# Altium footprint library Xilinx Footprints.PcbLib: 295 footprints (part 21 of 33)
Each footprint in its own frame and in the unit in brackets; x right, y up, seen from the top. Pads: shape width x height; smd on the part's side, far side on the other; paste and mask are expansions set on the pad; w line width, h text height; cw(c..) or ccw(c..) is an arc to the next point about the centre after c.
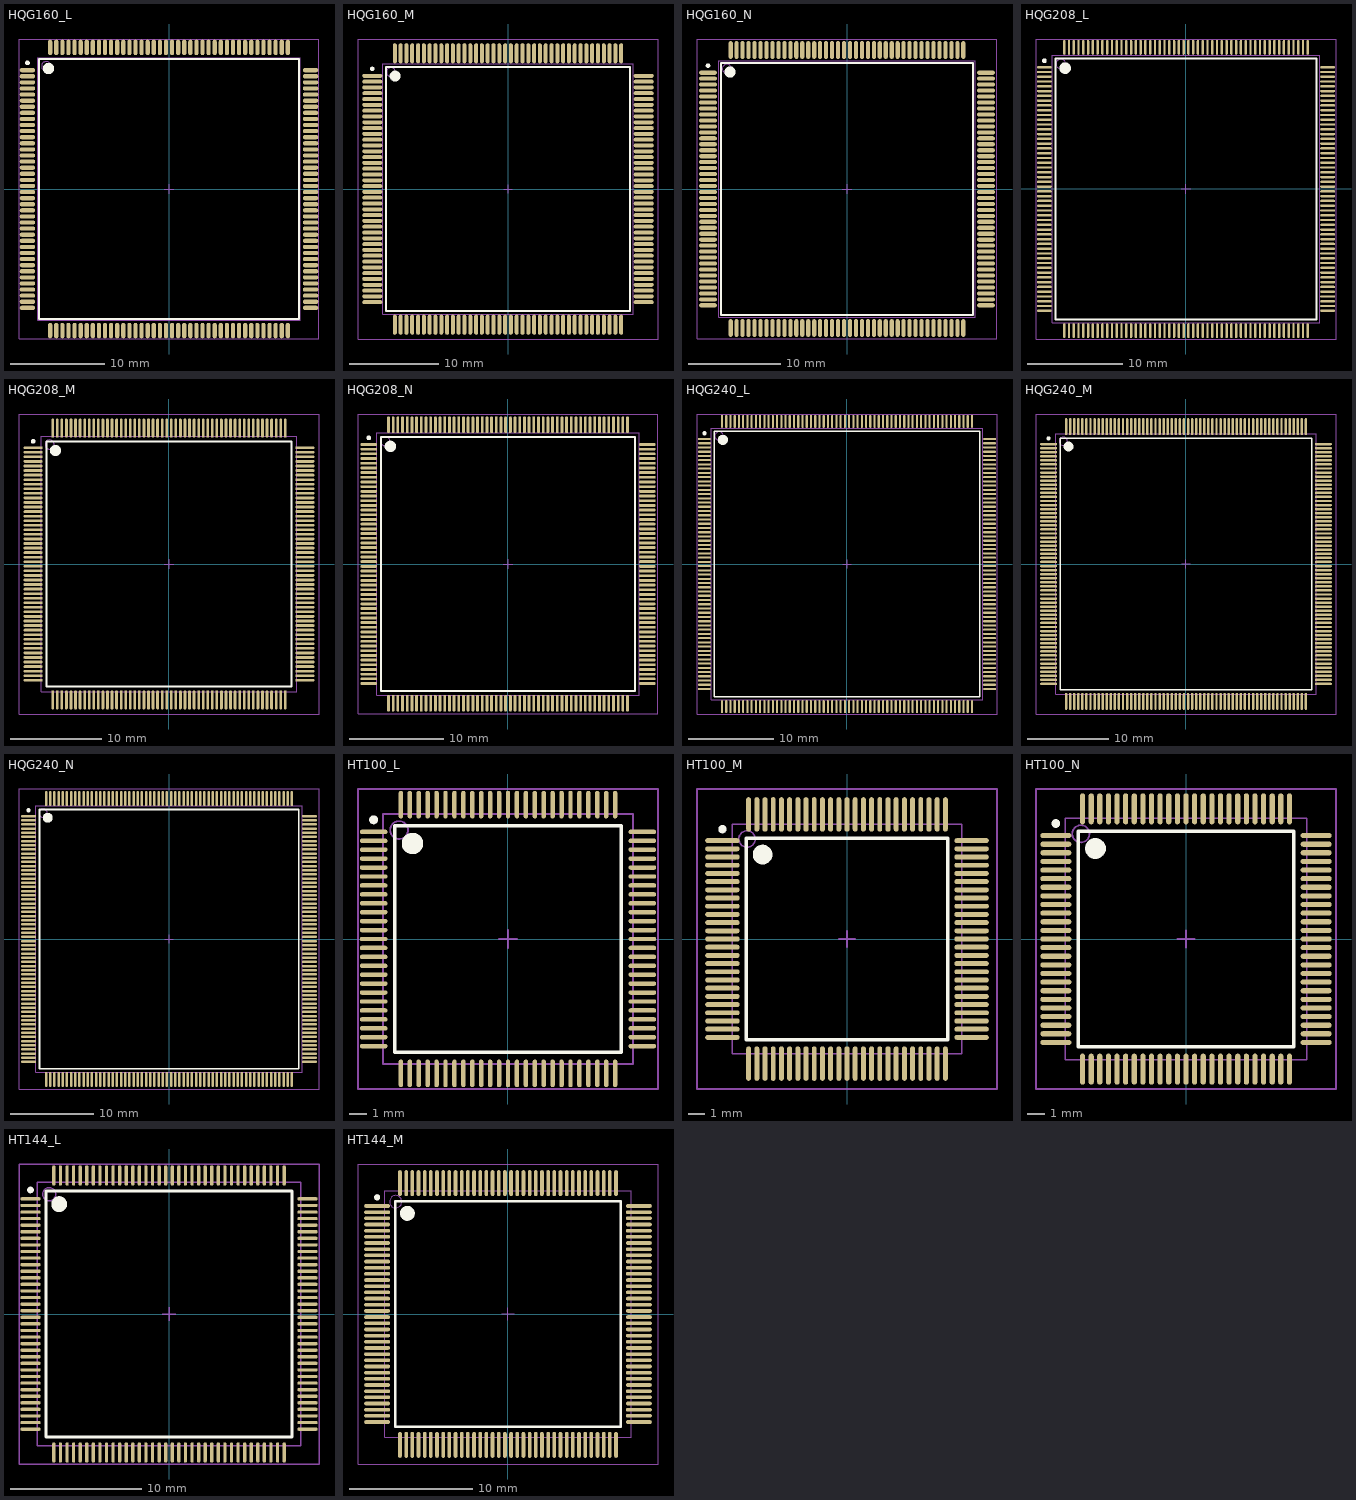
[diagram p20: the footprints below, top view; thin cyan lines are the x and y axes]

## HQG160_L [mm] "160-Pin Heat Sink Quad Flat Pack (HQG160) - Pb-Free, IPC High Density"
height 4.1
pads (160):
  oval 1.65x0.45 smd: 1(-15.1,12.675) 2(-15.1,12.025) 3(-15.1,11.375) 4(-15.1,10.725) 5(-15.1,10.075) 6(-15.1,9.425) 7(-15.1,8.775) 8(-15.1,8.125) 9(-15.1,7.475) 10(-15.1,6.825) 11(-15.1,6.175) 12(-15.1,5.525) 13(-15.1,4.875) 14(-15.1,4.225) 15(-15.1,3.575) 16(-15.1,2.925) 17(-15.1,2.275) 18(-15.1,1.625) 19(-15.1,0.975) 20(-15.1,0.325) 21(-15.1,-0.325) 22(-15.1,-0.975) 23(-15.1,-1.625) 24(-15.1,-2.275) 25(-15.1,-2.925) 26(-15.1,-3.575) 27(-15.1,-4.225) 28(-15.1,-4.875) 29(-15.1,-5.525) 30(-15.1,-6.175) 31(-15.1,-6.825) 32(-15.1,-7.475) 33(-15.1,-8.125) 34(-15.1,-8.775) 35(-15.1,-9.425) 36(-15.1,-10.075) 37(-15.1,-10.725) 38(-15.1,-11.375) 39(-15.1,-12.025) 40(-15.1,-12.675) 81(15.1,-12.675) 82(15.1,-12.025) 83(15.1,-11.375) 84(15.1,-10.725) 85(15.1,-10.075) 86(15.1,-9.425) 87(15.1,-8.775) 88(15.1,-8.125) 89(15.1,-7.475) 90(15.1,-6.825) 91(15.1,-6.175) 92(15.1,-5.525) 93(15.1,-4.875) 94(15.1,-4.225) 95(15.1,-3.575) 96(15.1,-2.925) 97(15.1,-2.275) 98(15.1,-1.625) 99(15.1,-0.975) 100(15.1,-0.325) 101(15.1,0.325) 102(15.1,0.975) 103(15.1,1.625) 104(15.1,2.275) 105(15.1,2.925) 106(15.1,3.575) 107(15.1,4.225) 108(15.1,4.875) 109(15.1,5.525) 110(15.1,6.175) 111(15.1,6.825) 112(15.1,7.475) 113(15.1,8.125) 114(15.1,8.775) 115(15.1,9.425) 116(15.1,10.075) 117(15.1,10.725) 118(15.1,11.375) 119(15.1,12.025) 120(15.1,12.675)
  oval 0.45x1.65 smd: 41(-12.675,-15.1) 42(-12.025,-15.1) 43(-11.375,-15.1) 44(-10.725,-15.1) 45(-10.075,-15.1) 46(-9.425,-15.1) 47(-8.775,-15.1) 48(-8.125,-15.1) 49(-7.475,-15.1) 50(-6.825,-15.1) 51(-6.175,-15.1) 52(-5.525,-15.1) 53(-4.875,-15.1) 54(-4.225,-15.1) 55(-3.575,-15.1) 56(-2.925,-15.1) 57(-2.275,-15.1) 58(-1.625,-15.1) 59(-0.975,-15.1) 60(-0.325,-15.1) 61(0.325,-15.1) 62(0.975,-15.1) 63(1.625,-15.1) 64(2.275,-15.1) 65(2.925,-15.1) 66(3.575,-15.1) 67(4.225,-15.1) 68(4.875,-15.1) 69(5.525,-15.1) 70(6.175,-15.1) 71(6.825,-15.1) 72(7.475,-15.1) 73(8.125,-15.1) 74(8.775,-15.1) 75(9.425,-15.1) 76(10.075,-15.1) 77(10.725,-15.1) 78(11.375,-15.1) 79(12.025,-15.1) 80(12.675,-15.1) 121(12.675,15.1) 122(12.025,15.1) 123(11.375,15.1) 124(10.725,15.1) 125(10.075,15.1) 126(9.425,15.1) 127(8.775,15.1) 128(8.125,15.1) 129(7.475,15.1) 130(6.825,15.1) 131(6.175,15.1) 132(5.525,15.1) 133(4.875,15.1) 134(4.225,15.1) 135(3.575,15.1) 136(2.925,15.1) 137(2.275,15.1) 138(1.625,15.1) 139(0.975,15.1) 140(0.325,15.1) 141(-0.325,15.1) 142(-0.975,15.1) 143(-1.625,15.1) 144(-2.275,15.1) 145(-2.925,15.1) 146(-3.575,15.1) 147(-4.225,15.1) 148(-4.875,15.1) 149(-5.525,15.1) 150(-6.175,15.1) 151(-6.825,15.1) 152(-7.475,15.1) 153(-8.125,15.1) 154(-8.775,15.1) 155(-9.425,15.1) 156(-10.075,15.1) 157(-10.725,15.1) 158(-11.375,15.1) 159(-12.025,15.1) 160(-12.675,15.1)
Top Overlay:
  circle w0.6: c-12.85,12.85 r0.3
  circle w0.25: c-15.1,13.45 r0.125
  lines w0.2: -13.85,-13.85 13.85,-13.85 13.85,13.85 -13.85,13.85 -13.85,-13.85
Mechanical 13:
  circle w0.1: c-13.1,13.1 r0.5
  lines w0.1: -14,-14 14,-14 14,14 -14,14 -14,-14
Mechanical 15:
  lines w0.1: -0.5,0 0.5,0 ; 0,-0.5 0,0.5 ; -16,-16 16,-16 16,16 -16,16 -16,-16
3D body: height 4.1, standoff 0, extent -14,-14 14,14

## HQG160_M [mm] "160-Pin Heat Sink Quad Flat Pack (HQG160) - Pb-Free, IPC Low Density"
height 4.1
pads (160):
  oval 2.25x0.45 smd: 1(-15.2,12.675) 2(-15.2,12.025) 3(-15.2,11.375) 4(-15.2,10.725) 5(-15.2,10.075) 6(-15.2,9.425) 7(-15.2,8.775) 8(-15.2,8.125) 9(-15.2,7.475) 10(-15.2,6.825) 11(-15.2,6.175) 12(-15.2,5.525) 13(-15.2,4.875) 14(-15.2,4.225) 15(-15.2,3.575) 16(-15.2,2.925) 17(-15.2,2.275) 18(-15.2,1.625) 19(-15.2,0.975) 20(-15.2,0.325) 21(-15.2,-0.325) 22(-15.2,-0.975) 23(-15.2,-1.625) 24(-15.2,-2.275) 25(-15.2,-2.925) 26(-15.2,-3.575) 27(-15.2,-4.225) 28(-15.2,-4.875) 29(-15.2,-5.525) 30(-15.2,-6.175) 31(-15.2,-6.825) 32(-15.2,-7.475) 33(-15.2,-8.125) 34(-15.2,-8.775) 35(-15.2,-9.425) 36(-15.2,-10.075) 37(-15.2,-10.725) 38(-15.2,-11.375) 39(-15.2,-12.025) 40(-15.2,-12.675) 81(15.2,-12.675) 82(15.2,-12.025) 83(15.2,-11.375) 84(15.2,-10.725) 85(15.2,-10.075) 86(15.2,-9.425) 87(15.2,-8.775) 88(15.2,-8.125) 89(15.2,-7.475) 90(15.2,-6.825) 91(15.2,-6.175) 92(15.2,-5.525) 93(15.2,-4.875) 94(15.2,-4.225) 95(15.2,-3.575) 96(15.2,-2.925) 97(15.2,-2.275) 98(15.2,-1.625) 99(15.2,-0.975) 100(15.2,-0.325) 101(15.2,0.325) 102(15.2,0.975) 103(15.2,1.625) 104(15.2,2.275) 105(15.2,2.925) 106(15.2,3.575) 107(15.2,4.225) 108(15.2,4.875) 109(15.2,5.525) 110(15.2,6.175) 111(15.2,6.825) 112(15.2,7.475) 113(15.2,8.125) 114(15.2,8.775) 115(15.2,9.425) 116(15.2,10.075) 117(15.2,10.725) 118(15.2,11.375) 119(15.2,12.025) 120(15.2,12.675)
  oval 0.45x2.25 smd: 41(-12.675,-15.2) 42(-12.025,-15.2) 43(-11.375,-15.2) 44(-10.725,-15.2) 45(-10.075,-15.2) 46(-9.425,-15.2) 47(-8.775,-15.2) 48(-8.125,-15.2) 49(-7.475,-15.2) 50(-6.825,-15.2) 51(-6.175,-15.2) 52(-5.525,-15.2) 53(-4.875,-15.2) 54(-4.225,-15.2) 55(-3.575,-15.2) 56(-2.925,-15.2) 57(-2.275,-15.2) 58(-1.625,-15.2) 59(-0.975,-15.2) 60(-0.325,-15.2) 61(0.325,-15.2) 62(0.975,-15.2) 63(1.625,-15.2) 64(2.275,-15.2) 65(2.925,-15.2) 66(3.575,-15.2) 67(4.225,-15.2) 68(4.875,-15.2) 69(5.525,-15.2) 70(6.175,-15.2) 71(6.825,-15.2) 72(7.475,-15.2) 73(8.125,-15.2) 74(8.775,-15.2) 75(9.425,-15.2) 76(10.075,-15.2) 77(10.725,-15.2) 78(11.375,-15.2) 79(12.025,-15.2) 80(12.675,-15.2) 121(12.675,15.2) 122(12.025,15.2) 123(11.375,15.2) 124(10.725,15.2) 125(10.075,15.2) 126(9.425,15.2) 127(8.775,15.2) 128(8.125,15.2) 129(7.475,15.2) 130(6.825,15.2) 131(6.175,15.2) 132(5.525,15.2) 133(4.875,15.2) 134(4.225,15.2) 135(3.575,15.2) 136(2.925,15.2) 137(2.275,15.2) 138(1.625,15.2) 139(0.975,15.2) 140(0.325,15.2) 141(-0.325,15.2) 142(-0.975,15.2) 143(-1.625,15.2) 144(-2.275,15.2) 145(-2.925,15.2) 146(-3.575,15.2) 147(-4.225,15.2) 148(-4.875,15.2) 149(-5.525,15.2) 150(-6.175,15.2) 151(-6.825,15.2) 152(-7.475,15.2) 153(-8.125,15.2) 154(-8.775,15.2) 155(-9.425,15.2) 156(-10.075,15.2) 157(-10.725,15.2) 158(-11.375,15.2) 159(-12.025,15.2) 160(-12.675,15.2)
Top Overlay:
  circle w0.6: c-12.65,12.65 r0.3
  circle w0.25: c-15.2,13.45 r0.125
  lines w0.2: -13.65,-13.65 13.65,-13.65 13.65,13.65 -13.65,13.65 -13.65,-13.65
Mechanical 13:
  circle w0.1: c-13.1,13.1 r0.5
  lines w0.1: -14,-14 14,-14 14,14 -14,14 -14,-14
Mechanical 15:
  lines w0.1: -0.5,0 0.5,0 ; 0,-0.5 0,0.5 ; -16.8,-16.8 16.8,-16.8 16.8,16.8 -16.8,16.8 -16.8,-16.8
3D body: height 4.1, standoff 0, extent -14,-14 14,14

## HQG160_N [mm] "160-Pin Heat Sink Quad Flat Pack (HQG160) - Pb-Free, IPC Medium Density"
height 4.1
pads (160):
  oval 1.95x0.45 smd: 1(-15.15,12.675) 2(-15.15,12.025) 3(-15.15,11.375) 4(-15.15,10.725) 5(-15.15,10.075) 6(-15.15,9.425) 7(-15.15,8.775) 8(-15.15,8.125) 9(-15.15,7.475) 10(-15.15,6.825) 11(-15.15,6.175) 12(-15.15,5.525) 13(-15.15,4.875) 14(-15.15,4.225) 15(-15.15,3.575) 16(-15.15,2.925) 17(-15.15,2.275) 18(-15.15,1.625) 19(-15.15,0.975) 20(-15.15,0.325) 21(-15.15,-0.325) 22(-15.15,-0.975) 23(-15.15,-1.625) 24(-15.15,-2.275) 25(-15.15,-2.925) 26(-15.15,-3.575) 27(-15.15,-4.225) 28(-15.15,-4.875) 29(-15.15,-5.525) 30(-15.15,-6.175) 31(-15.15,-6.825) 32(-15.15,-7.475) 33(-15.15,-8.125) 34(-15.15,-8.775) 35(-15.15,-9.425) 36(-15.15,-10.075) 37(-15.15,-10.725) 38(-15.15,-11.375) 39(-15.15,-12.025) 40(-15.15,-12.675) 81(15.15,-12.675) 82(15.15,-12.025) 83(15.15,-11.375) 84(15.15,-10.725) 85(15.15,-10.075) 86(15.15,-9.425) 87(15.15,-8.775) 88(15.15,-8.125) 89(15.15,-7.475) 90(15.15,-6.825) 91(15.15,-6.175) 92(15.15,-5.525) 93(15.15,-4.875) 94(15.15,-4.225) 95(15.15,-3.575) 96(15.15,-2.925) 97(15.15,-2.275) 98(15.15,-1.625) 99(15.15,-0.975) 100(15.15,-0.325) 101(15.15,0.325) 102(15.15,0.975) 103(15.15,1.625) 104(15.15,2.275) 105(15.15,2.925) 106(15.15,3.575) 107(15.15,4.225) 108(15.15,4.875) 109(15.15,5.525) 110(15.15,6.175) 111(15.15,6.825) 112(15.15,7.475) 113(15.15,8.125) 114(15.15,8.775) 115(15.15,9.425) 116(15.15,10.075) 117(15.15,10.725) 118(15.15,11.375) 119(15.15,12.025) 120(15.15,12.675)
  oval 0.45x1.95 smd: 41(-12.675,-15.15) 42(-12.025,-15.15) 43(-11.375,-15.15) 44(-10.725,-15.15) 45(-10.075,-15.15) 46(-9.425,-15.15) 47(-8.775,-15.15) 48(-8.125,-15.15) 49(-7.475,-15.15) 50(-6.825,-15.15) 51(-6.175,-15.15) 52(-5.525,-15.15) 53(-4.875,-15.15) 54(-4.225,-15.15) 55(-3.575,-15.15) 56(-2.925,-15.15) 57(-2.275,-15.15) 58(-1.625,-15.15) 59(-0.975,-15.15) 60(-0.325,-15.15) 61(0.325,-15.15) 62(0.975,-15.15) 63(1.625,-15.15) 64(2.275,-15.15) 65(2.925,-15.15) 66(3.575,-15.15) 67(4.225,-15.15) 68(4.875,-15.15) 69(5.525,-15.15) 70(6.175,-15.15) 71(6.825,-15.15) 72(7.475,-15.15) 73(8.125,-15.15) 74(8.775,-15.15) 75(9.425,-15.15) 76(10.075,-15.15) 77(10.725,-15.15) 78(11.375,-15.15) 79(12.025,-15.15) 80(12.675,-15.15) 121(12.675,15.15) 122(12.025,15.15) 123(11.375,15.15) 124(10.725,15.15) 125(10.075,15.15) 126(9.425,15.15) 127(8.775,15.15) 128(8.125,15.15) 129(7.475,15.15) 130(6.825,15.15) 131(6.175,15.15) 132(5.525,15.15) 133(4.875,15.15) 134(4.225,15.15) 135(3.575,15.15) 136(2.925,15.15) 137(2.275,15.15) 138(1.625,15.15) 139(0.975,15.15) 140(0.325,15.15) 141(-0.325,15.15) 142(-0.975,15.15) 143(-1.625,15.15) 144(-2.275,15.15) 145(-2.925,15.15) 146(-3.575,15.15) 147(-4.225,15.15) 148(-4.875,15.15) 149(-5.525,15.15) 150(-6.175,15.15) 151(-6.825,15.15) 152(-7.475,15.15) 153(-8.125,15.15) 154(-8.775,15.15) 155(-9.425,15.15) 156(-10.075,15.15) 157(-10.725,15.15) 158(-11.375,15.15) 159(-12.025,15.15) 160(-12.675,15.15)
Top Overlay:
  circle w0.6: c-12.75,12.75 r0.3
  circle w0.25: c-15.15,13.45 r0.125
  lines w0.2: -13.75,-13.75 13.75,-13.75 13.75,13.75 -13.75,13.75 -13.75,-13.75
Mechanical 13:
  circle w0.1: c-13.1,13.1 r0.5
  lines w0.1: -14,-14 14,-14 14,14 -14,14 -14,-14
Mechanical 15:
  lines w0.1: -0.5,0 0.5,0 ; 0,-0.5 0,0.5 ; -16.35,-16.35 16.35,-16.35 16.35,16.35 -16.35,16.35 -16.35,-16.35
3D body: height 4.1, standoff 0, extent -14,-14 14,14

## HQG208_L [mm] "208-Pin Heat Sink Quad Flat Pack (HQG208) - Pb-Free, IPC High Density"
height 4.1
pads (208):
  oval 1.55x0.25 smd: 1(-14.825,12.75) 2(-14.825,12.25) 3(-14.825,11.75) 4(-14.825,11.25) 5(-14.825,10.75) 6(-14.825,10.25) 7(-14.825,9.75) 8(-14.825,9.25) 9(-14.825,8.75) 10(-14.825,8.25) 11(-14.825,7.75) 12(-14.825,7.25) 13(-14.825,6.75) 14(-14.825,6.25) 15(-14.825,5.75) 16(-14.825,5.25) 17(-14.825,4.75) 18(-14.825,4.25) 19(-14.825,3.75) 20(-14.825,3.25) 21(-14.825,2.75) 22(-14.825,2.25) 23(-14.825,1.75) 24(-14.825,1.25) 25(-14.825,0.75) 26(-14.825,0.25) 27(-14.825,-0.25) 28(-14.825,-0.75) 29(-14.825,-1.25) 30(-14.825,-1.75) 31(-14.825,-2.25) 32(-14.825,-2.75) 33(-14.825,-3.25) 34(-14.825,-3.75) 35(-14.825,-4.25) 36(-14.825,-4.75) 37(-14.825,-5.25) 38(-14.825,-5.75) 39(-14.825,-6.25) 40(-14.825,-6.75) 41(-14.825,-7.25) 42(-14.825,-7.75) 43(-14.825,-8.25) 44(-14.825,-8.75) 45(-14.825,-9.25) 46(-14.825,-9.75) 47(-14.825,-10.25) 48(-14.825,-10.75) 49(-14.825,-11.25) 50(-14.825,-11.75) 51(-14.825,-12.25) 52(-14.825,-12.75) 105(14.825,-12.75) 106(14.825,-12.25) 107(14.825,-11.75) 108(14.825,-11.25) 109(14.825,-10.75) 110(14.825,-10.25) 111(14.825,-9.75) 112(14.825,-9.25) 113(14.825,-8.75) 114(14.825,-8.25) 115(14.825,-7.75) 116(14.825,-7.25) 117(14.825,-6.75) 118(14.825,-6.25) 119(14.825,-5.75) 120(14.825,-5.25) 121(14.825,-4.75) 122(14.825,-4.25) 123(14.825,-3.75) 124(14.825,-3.25) 125(14.825,-2.75) 126(14.825,-2.25) 127(14.825,-1.75) 128(14.825,-1.25) 129(14.825,-0.75) 130(14.825,-0.25) 131(14.825,0.25) 132(14.825,0.75) 133(14.825,1.25) 134(14.825,1.75) 135(14.825,2.25) 136(14.825,2.75) 137(14.825,3.25) 138(14.825,3.75) 139(14.825,4.25) 140(14.825,4.75) 141(14.825,5.25) 142(14.825,5.75) 143(14.825,6.25) 144(14.825,6.75) 145(14.825,7.25) 146(14.825,7.75) 147(14.825,8.25) 148(14.825,8.75) 149(14.825,9.25) 150(14.825,9.75) 151(14.825,10.25) 152(14.825,10.75) 153(14.825,11.25) 154(14.825,11.75) 155(14.825,12.25) 156(14.825,12.75)
  oval 0.25x1.55 smd: 53(-12.75,-14.825) 54(-12.25,-14.825) 55(-11.75,-14.825) 56(-11.25,-14.825) 57(-10.75,-14.825) 58(-10.25,-14.825) 59(-9.75,-14.825) 60(-9.25,-14.825) 61(-8.75,-14.825) 62(-8.25,-14.825) 63(-7.75,-14.825) 64(-7.25,-14.825) 65(-6.75,-14.825) 66(-6.25,-14.825) 67(-5.75,-14.825) 68(-5.25,-14.825) 69(-4.75,-14.825) 70(-4.25,-14.825) 71(-3.75,-14.825) 72(-3.25,-14.825) 73(-2.75,-14.825) 74(-2.25,-14.825) 75(-1.75,-14.825) 76(-1.25,-14.825) 77(-0.75,-14.825) 78(-0.25,-14.825) 79(0.25,-14.825) 80(0.75,-14.825) 81(1.25,-14.825) 82(1.75,-14.825) 83(2.25,-14.825) 84(2.75,-14.825) 85(3.25,-14.825) 86(3.75,-14.825) 87(4.25,-14.825) 88(4.75,-14.825) 89(5.25,-14.825) 90(5.75,-14.825) 91(6.25,-14.825) 92(6.75,-14.825) 93(7.25,-14.825) 94(7.75,-14.825) 95(8.25,-14.825) 96(8.75,-14.825) 97(9.25,-14.825) 98(9.75,-14.825) 99(10.25,-14.825) 100(10.75,-14.825) 101(11.25,-14.825) 102(11.75,-14.825) 103(12.25,-14.825) 104(12.75,-14.825) 157(12.75,14.825) 158(12.25,14.825) 159(11.75,14.825) 160(11.25,14.825) 161(10.75,14.825) 162(10.25,14.825) 163(9.75,14.825) 164(9.25,14.825) 165(8.75,14.825) 166(8.25,14.825) 167(7.75,14.825) 168(7.25,14.825) 169(6.75,14.825) 170(6.25,14.825) 171(5.75,14.825) 172(5.25,14.825) 173(4.75,14.825) 174(4.25,14.825) 175(3.75,14.825) 176(3.25,14.825) 177(2.75,14.825) 178(2.25,14.825) 179(1.75,14.825) 180(1.25,14.825) 181(0.75,14.825) 182(0.25,14.825) 183(-0.25,14.825) 184(-0.75,14.825) 185(-1.25,14.825) 186(-1.75,14.825) 187(-2.25,14.825) 188(-2.75,14.825) 189(-3.25,14.825) 190(-3.75,14.825) 191(-4.25,14.825) 192(-4.75,14.825) 193(-5.25,14.825) 194(-5.75,14.825) 195(-6.25,14.825) 196(-6.75,14.825) 197(-7.25,14.825) 198(-7.75,14.825) 199(-8.25,14.825) 200(-8.75,14.825) 201(-9.25,14.825) 202(-9.75,14.825) 203(-10.25,14.825) 204(-10.75,14.825) 205(-11.25,14.825) 206(-11.75,14.825) 207(-12.25,14.825) 208(-12.75,14.825)
Top Overlay:
  circle w0.6: c-12.65,12.65 r0.3
  circle w0.25: c-14.825,13.425 r0.125
  lines w0.2: -13.65,-13.65 13.65,-13.65 13.65,13.65 -13.65,13.65 -13.65,-13.65
Mechanical 13:
  circle w0.1: c-13.1,13.1 r0.5
  lines w0.1: -14,-14 14,-14 14,14 -14,14 -14,-14
Mechanical 15:
  lines w0.1: -0.5,0 0.5,0 ; 0,-0.5 0,0.5 ; -15.7,-15.7 15.7,-15.7 15.7,15.7 -15.7,15.7 -15.7,-15.7
3D body: height 4.1, standoff 0, extent -14,-14 14,14

## HQG208_M [mm] "208-Pin Heat Sink Quad Flat Pack (HQG208) - Pb-Free, IPC Low Density"
height 4.1
pads (208):
  oval 2.1x0.3 smd: 1(-14.9,12.75) 2(-14.9,12.25) 3(-14.9,11.75) 4(-14.9,11.25) 5(-14.9,10.75) 6(-14.9,10.25) 7(-14.9,9.75) 8(-14.9,9.25) 9(-14.9,8.75) 10(-14.9,8.25) 11(-14.9,7.75) 12(-14.9,7.25) 13(-14.9,6.75) 14(-14.9,6.25) 15(-14.9,5.75) 16(-14.9,5.25) 17(-14.9,4.75) 18(-14.9,4.25) 19(-14.9,3.75) 20(-14.9,3.25) 21(-14.9,2.75) 22(-14.9,2.25) 23(-14.9,1.75) 24(-14.9,1.25) 25(-14.9,0.75) 26(-14.9,0.25) 27(-14.9,-0.25) 28(-14.9,-0.75) 29(-14.9,-1.25) 30(-14.9,-1.75) 31(-14.9,-2.25) 32(-14.9,-2.75) 33(-14.9,-3.25) 34(-14.9,-3.75) 35(-14.9,-4.25) 36(-14.9,-4.75) 37(-14.9,-5.25) 38(-14.9,-5.75) 39(-14.9,-6.25) 40(-14.9,-6.75) 41(-14.9,-7.25) 42(-14.9,-7.75) 43(-14.9,-8.25) 44(-14.9,-8.75) 45(-14.9,-9.25) 46(-14.9,-9.75) 47(-14.9,-10.25) 48(-14.9,-10.75) 49(-14.9,-11.25) 50(-14.9,-11.75) 51(-14.9,-12.25) 52(-14.9,-12.75) 105(14.9,-12.75) 106(14.9,-12.25) 107(14.9,-11.75) 108(14.9,-11.25) 109(14.9,-10.75) 110(14.9,-10.25) 111(14.9,-9.75) 112(14.9,-9.25) 113(14.9,-8.75) 114(14.9,-8.25) 115(14.9,-7.75) 116(14.9,-7.25) 117(14.9,-6.75) 118(14.9,-6.25) 119(14.9,-5.75) 120(14.9,-5.25) 121(14.9,-4.75) 122(14.9,-4.25) 123(14.9,-3.75) 124(14.9,-3.25) 125(14.9,-2.75) 126(14.9,-2.25) 127(14.9,-1.75) 128(14.9,-1.25) 129(14.9,-0.75) 130(14.9,-0.25) 131(14.9,0.25) 132(14.9,0.75) 133(14.9,1.25) 134(14.9,1.75) 135(14.9,2.25) 136(14.9,2.75) 137(14.9,3.25) 138(14.9,3.75) 139(14.9,4.25) 140(14.9,4.75) 141(14.9,5.25) 142(14.9,5.75) 143(14.9,6.25) 144(14.9,6.75) 145(14.9,7.25) 146(14.9,7.75) 147(14.9,8.25) 148(14.9,8.75) 149(14.9,9.25) 150(14.9,9.75) 151(14.9,10.25) 152(14.9,10.75) 153(14.9,11.25) 154(14.9,11.75) 155(14.9,12.25) 156(14.9,12.75)
  oval 0.3x2.1 smd: 53(-12.75,-14.9) 54(-12.25,-14.9) 55(-11.75,-14.9) 56(-11.25,-14.9) 57(-10.75,-14.9) 58(-10.25,-14.9) 59(-9.75,-14.9) 60(-9.25,-14.9) 61(-8.75,-14.9) 62(-8.25,-14.9) 63(-7.75,-14.9) 64(-7.25,-14.9) 65(-6.75,-14.9) 66(-6.25,-14.9) 67(-5.75,-14.9) 68(-5.25,-14.9) 69(-4.75,-14.9) 70(-4.25,-14.9) 71(-3.75,-14.9) 72(-3.25,-14.9) 73(-2.75,-14.9) 74(-2.25,-14.9) 75(-1.75,-14.9) 76(-1.25,-14.9) 77(-0.75,-14.9) 78(-0.25,-14.9) 79(0.25,-14.9) 80(0.75,-14.9) 81(1.25,-14.9) 82(1.75,-14.9) 83(2.25,-14.9) 84(2.75,-14.9) 85(3.25,-14.9) 86(3.75,-14.9) 87(4.25,-14.9) 88(4.75,-14.9) 89(5.25,-14.9) 90(5.75,-14.9) 91(6.25,-14.9) 92(6.75,-14.9) 93(7.25,-14.9) 94(7.75,-14.9) 95(8.25,-14.9) 96(8.75,-14.9) 97(9.25,-14.9) 98(9.75,-14.9) 99(10.25,-14.9) 100(10.75,-14.9) 101(11.25,-14.9) 102(11.75,-14.9) 103(12.25,-14.9) 104(12.75,-14.9) 157(12.75,14.9) 158(12.25,14.9) 159(11.75,14.9) 160(11.25,14.9) 161(10.75,14.9) 162(10.25,14.9) 163(9.75,14.9) 164(9.25,14.9) 165(8.75,14.9) 166(8.25,14.9) 167(7.75,14.9) 168(7.25,14.9) 169(6.75,14.9) 170(6.25,14.9) 171(5.75,14.9) 172(5.25,14.9) 173(4.75,14.9) 174(4.25,14.9) 175(3.75,14.9) 176(3.25,14.9) 177(2.75,14.9) 178(2.25,14.9) 179(1.75,14.9) 180(1.25,14.9) 181(0.75,14.9) 182(0.25,14.9) 183(-0.25,14.9) 184(-0.75,14.9) 185(-1.25,14.9) 186(-1.75,14.9) 187(-2.25,14.9) 188(-2.75,14.9) 189(-3.25,14.9) 190(-3.75,14.9) 191(-4.25,14.9) 192(-4.75,14.9) 193(-5.25,14.9) 194(-5.75,14.9) 195(-6.25,14.9) 196(-6.75,14.9) 197(-7.25,14.9) 198(-7.75,14.9) 199(-8.25,14.9) 200(-8.75,14.9) 201(-9.25,14.9) 202(-9.75,14.9) 203(-10.25,14.9) 204(-10.75,14.9) 205(-11.25,14.9) 206(-11.75,14.9) 207(-12.25,14.9) 208(-12.75,14.9)
Top Overlay:
  circle w0.6: c-12.45,12.45 r0.3
  circle w0.25: c-14.9,13.45 r0.125
  lines w0.2: -13.45,-13.45 13.45,-13.45 13.45,13.45 -13.45,13.45 -13.45,-13.45
Mechanical 13:
  circle w0.1: c-13.1,13.1 r0.5
  lines w0.1: -14,-14 14,-14 14,14 -14,14 -14,-14
Mechanical 15:
  lines w0.1: -0.5,0 0.5,0 ; 0,-0.5 0,0.5 ; -16.45,-16.45 16.45,-16.45 16.45,16.45 -16.45,16.45 -16.45,-16.45
3D body: height 4.1, standoff 0, extent -14,-14 14,14

## HQG208_N [mm] "208-Pin Heat Sink Quad Flat Pack (HQG208) - Pb-Free, IPC Medium Density"
height 4.1
pads (208):
  oval 1.8x0.3 smd: 1(-14.85,12.75) 2(-14.85,12.25) 3(-14.85,11.75) 4(-14.85,11.25) 5(-14.85,10.75) 6(-14.85,10.25) 7(-14.85,9.75) 8(-14.85,9.25) 9(-14.85,8.75) 10(-14.85,8.25) 11(-14.85,7.75) 12(-14.85,7.25) 13(-14.85,6.75) 14(-14.85,6.25) 15(-14.85,5.75) 16(-14.85,5.25) 17(-14.85,4.75) 18(-14.85,4.25) 19(-14.85,3.75) 20(-14.85,3.25) 21(-14.85,2.75) 22(-14.85,2.25) 23(-14.85,1.75) 24(-14.85,1.25) 25(-14.85,0.75) 26(-14.85,0.25) 27(-14.85,-0.25) 28(-14.85,-0.75) 29(-14.85,-1.25) 30(-14.85,-1.75) 31(-14.85,-2.25) 32(-14.85,-2.75) 33(-14.85,-3.25) 34(-14.85,-3.75) 35(-14.85,-4.25) 36(-14.85,-4.75) 37(-14.85,-5.25) 38(-14.85,-5.75) 39(-14.85,-6.25) 40(-14.85,-6.75) 41(-14.85,-7.25) 42(-14.85,-7.75) 43(-14.85,-8.25) 44(-14.85,-8.75) 45(-14.85,-9.25) 46(-14.85,-9.75) 47(-14.85,-10.25) 48(-14.85,-10.75) 49(-14.85,-11.25) 50(-14.85,-11.75) 51(-14.85,-12.25) 52(-14.85,-12.75) 105(14.85,-12.75) 106(14.85,-12.25) 107(14.85,-11.75) 108(14.85,-11.25) 109(14.85,-10.75) 110(14.85,-10.25) 111(14.85,-9.75) 112(14.85,-9.25) 113(14.85,-8.75) 114(14.85,-8.25) 115(14.85,-7.75) 116(14.85,-7.25) 117(14.85,-6.75) 118(14.85,-6.25) 119(14.85,-5.75) 120(14.85,-5.25) 121(14.85,-4.75) 122(14.85,-4.25) 123(14.85,-3.75) 124(14.85,-3.25) 125(14.85,-2.75) 126(14.85,-2.25) 127(14.85,-1.75) 128(14.85,-1.25) 129(14.85,-0.75) 130(14.85,-0.25) 131(14.85,0.25) 132(14.85,0.75) 133(14.85,1.25) 134(14.85,1.75) 135(14.85,2.25) 136(14.85,2.75) 137(14.85,3.25) 138(14.85,3.75) 139(14.85,4.25) 140(14.85,4.75) 141(14.85,5.25) 142(14.85,5.75) 143(14.85,6.25) 144(14.85,6.75) 145(14.85,7.25) 146(14.85,7.75) 147(14.85,8.25) 148(14.85,8.75) 149(14.85,9.25) 150(14.85,9.75) 151(14.85,10.25) 152(14.85,10.75) 153(14.85,11.25) 154(14.85,11.75) 155(14.85,12.25) 156(14.85,12.75)
  oval 0.3x1.8 smd: 53(-12.75,-14.85) 54(-12.25,-14.85) 55(-11.75,-14.85) 56(-11.25,-14.85) 57(-10.75,-14.85) 58(-10.25,-14.85) 59(-9.75,-14.85) 60(-9.25,-14.85) 61(-8.75,-14.85) 62(-8.25,-14.85) 63(-7.75,-14.85) 64(-7.25,-14.85) 65(-6.75,-14.85) 66(-6.25,-14.85) 67(-5.75,-14.85) 68(-5.25,-14.85) 69(-4.75,-14.85) 70(-4.25,-14.85) 71(-3.75,-14.85) 72(-3.25,-14.85) 73(-2.75,-14.85) 74(-2.25,-14.85) 75(-1.75,-14.85) 76(-1.25,-14.85) 77(-0.75,-14.85) 78(-0.25,-14.85) 79(0.25,-14.85) 80(0.75,-14.85) 81(1.25,-14.85) 82(1.75,-14.85) 83(2.25,-14.85) 84(2.75,-14.85) 85(3.25,-14.85) 86(3.75,-14.85) 87(4.25,-14.85) 88(4.75,-14.85) 89(5.25,-14.85) 90(5.75,-14.85) 91(6.25,-14.85) 92(6.75,-14.85) 93(7.25,-14.85) 94(7.75,-14.85) 95(8.25,-14.85) 96(8.75,-14.85) 97(9.25,-14.85) 98(9.75,-14.85) 99(10.25,-14.85) 100(10.75,-14.85) 101(11.25,-14.85) 102(11.75,-14.85) 103(12.25,-14.85) 104(12.75,-14.85) 157(12.75,14.85) 158(12.25,14.85) 159(11.75,14.85) 160(11.25,14.85) 161(10.75,14.85) 162(10.25,14.85) 163(9.75,14.85) 164(9.25,14.85) 165(8.75,14.85) 166(8.25,14.85) 167(7.75,14.85) 168(7.25,14.85) 169(6.75,14.85) 170(6.25,14.85) 171(5.75,14.85) 172(5.25,14.85) 173(4.75,14.85) 174(4.25,14.85) 175(3.75,14.85) 176(3.25,14.85) 177(2.75,14.85) 178(2.25,14.85) 179(1.75,14.85) 180(1.25,14.85) 181(0.75,14.85) 182(0.25,14.85) 183(-0.25,14.85) 184(-0.75,14.85) 185(-1.25,14.85) 186(-1.75,14.85) 187(-2.25,14.85) 188(-2.75,14.85) 189(-3.25,14.85) 190(-3.75,14.85) 191(-4.25,14.85) 192(-4.75,14.85) 193(-5.25,14.85) 194(-5.75,14.85) 195(-6.25,14.85) 196(-6.75,14.85) 197(-7.25,14.85) 198(-7.75,14.85) 199(-8.25,14.85) 200(-8.75,14.85) 201(-9.25,14.85) 202(-9.75,14.85) 203(-10.25,14.85) 204(-10.75,14.85) 205(-11.25,14.85) 206(-11.75,14.85) 207(-12.25,14.85) 208(-12.75,14.85)
Top Overlay:
  circle w0.6: c-12.55,12.55 r0.3
  circle w0.25: c-14.85,13.45 r0.125
  lines w0.2: -13.55,-13.55 13.55,-13.55 13.55,13.55 -13.55,13.55 -13.55,-13.55
Mechanical 13:
  circle w0.1: c-13.1,13.1 r0.5
  lines w0.1: -14,-14 14,-14 14,14 -14,14 -14,-14
Mechanical 15:
  lines w0.1: -0.5,0 0.5,0 ; 0,-0.5 0,0.5 ; -16,-16 16,-16 16,16 -16,16 -16,-16
3D body: height 4.1, standoff 0, extent -14,-14 14,14

## HQG240_L [mm] "240-Pin Heat Sink Quad Flat Pack (HQG240) - Pb-Free, IPC High Density"
height 4.1
pads (240):
  oval 1.55x0.25 smd: 1(-16.825,14.75) 2(-16.825,14.25) 3(-16.825,13.75) 4(-16.825,13.25) 5(-16.825,12.75) 6(-16.825,12.25) 7(-16.825,11.75) 8(-16.825,11.25) 9(-16.825,10.75) 10(-16.825,10.25) 11(-16.825,9.75) 12(-16.825,9.25) 13(-16.825,8.75) 14(-16.825,8.25) 15(-16.825,7.75) 16(-16.825,7.25) 17(-16.825,6.75) 18(-16.825,6.25) 19(-16.825,5.75) 20(-16.825,5.25) 21(-16.825,4.75) 22(-16.825,4.25) 23(-16.825,3.75) 24(-16.825,3.25) 25(-16.825,2.75) 26(-16.825,2.25) 27(-16.825,1.75) 28(-16.825,1.25) 29(-16.825,0.75) 30(-16.825,0.25) 31(-16.825,-0.25) 32(-16.825,-0.75) 33(-16.825,-1.25) 34(-16.825,-1.75) 35(-16.825,-2.25) 36(-16.825,-2.75) 37(-16.825,-3.25) 38(-16.825,-3.75) 39(-16.825,-4.25) 40(-16.825,-4.75) 41(-16.825,-5.25) 42(-16.825,-5.75) 43(-16.825,-6.25) 44(-16.825,-6.75) 45(-16.825,-7.25) 46(-16.825,-7.75) 47(-16.825,-8.25) 48(-16.825,-8.75) 49(-16.825,-9.25) 50(-16.825,-9.75) 51(-16.825,-10.25) 52(-16.825,-10.75) 53(-16.825,-11.25) 54(-16.825,-11.75) 55(-16.825,-12.25) 56(-16.825,-12.75) 57(-16.825,-13.25) 58(-16.825,-13.75) 59(-16.825,-14.25) 60(-16.825,-14.75) 121(16.825,-14.75) 122(16.825,-14.25) 123(16.825,-13.75) 124(16.825,-13.25) 125(16.825,-12.75) 126(16.825,-12.25) 127(16.825,-11.75) 128(16.825,-11.25) 129(16.825,-10.75) 130(16.825,-10.25) 131(16.825,-9.75) 132(16.825,-9.25) 133(16.825,-8.75) 134(16.825,-8.25) 135(16.825,-7.75) 136(16.825,-7.25) 137(16.825,-6.75) 138(16.825,-6.25) 139(16.825,-5.75) 140(16.825,-5.25) 141(16.825,-4.75) 142(16.825,-4.25) 143(16.825,-3.75) 144(16.825,-3.25) 145(16.825,-2.75) 146(16.825,-2.25) 147(16.825,-1.75) 148(16.825,-1.25) 149(16.825,-0.75) 150(16.825,-0.25) 151(16.825,0.25) 152(16.825,0.75) 153(16.825,1.25) 154(16.825,1.75) 155(16.825,2.25) 156(16.825,2.75) 157(16.825,3.25) 158(16.825,3.75) 159(16.825,4.25) 160(16.825,4.75) 161(16.825,5.25) 162(16.825,5.75) 163(16.825,6.25) 164(16.825,6.75) 165(16.825,7.25) 166(16.825,7.75) 167(16.825,8.25) 168(16.825,8.75) 169(16.825,9.25) 170(16.825,9.75) 171(16.825,10.25) 172(16.825,10.75) 173(16.825,11.25) 174(16.825,11.75) 175(16.825,12.25) 176(16.825,12.75) 177(16.825,13.25) 178(16.825,13.75) 179(16.825,14.25) 180(16.825,14.75)
  oval 0.25x1.55 smd: 61(-14.75,-16.825) 62(-14.25,-16.825) 63(-13.75,-16.825) 64(-13.25,-16.825) 65(-12.75,-16.825) 66(-12.25,-16.825) 67(-11.75,-16.825) 68(-11.25,-16.825) 69(-10.75,-16.825) 70(-10.25,-16.825) 71(-9.75,-16.825) 72(-9.25,-16.825) 73(-8.75,-16.825) 74(-8.25,-16.825) 75(-7.75,-16.825) 76(-7.25,-16.825) 77(-6.75,-16.825) 78(-6.25,-16.825) 79(-5.75,-16.825) 80(-5.25,-16.825) 81(-4.75,-16.825) 82(-4.25,-16.825) 83(-3.75,-16.825) 84(-3.25,-16.825) 85(-2.75,-16.825) 86(-2.25,-16.825) 87(-1.75,-16.825) 88(-1.25,-16.825) 89(-0.75,-16.825) 90(-0.25,-16.825) 91(0.25,-16.825) 92(0.75,-16.825) 93(1.25,-16.825) 94(1.75,-16.825) 95(2.25,-16.825) 96(2.75,-16.825) 97(3.25,-16.825) 98(3.75,-16.825) 99(4.25,-16.825) 100(4.75,-16.825) 101(5.25,-16.825) 102(5.75,-16.825) 103(6.25,-16.825) 104(6.75,-16.825) 105(7.25,-16.825) 106(7.75,-16.825) 107(8.25,-16.825) 108(8.75,-16.825) 109(9.25,-16.825) 110(9.75,-16.825) 111(10.25,-16.825) 112(10.75,-16.825) 113(11.25,-16.825) 114(11.75,-16.825) 115(12.25,-16.825) 116(12.75,-16.825) 117(13.25,-16.825) 118(13.75,-16.825) 119(14.25,-16.825) 120(14.75,-16.825) 181(14.75,16.825) 182(14.25,16.825) 183(13.75,16.825) 184(13.25,16.825) 185(12.75,16.825) 186(12.25,16.825) 187(11.75,16.825) 188(11.25,16.825) 189(10.75,16.825) 190(10.25,16.825) 191(9.75,16.825) 192(9.25,16.825) 193(8.75,16.825) 194(8.25,16.825) 195(7.75,16.825) 196(7.25,16.825) 197(6.75,16.825) 198(6.25,16.825) 199(5.75,16.825) 200(5.25,16.825) 201(4.75,16.825) 202(4.25,16.825) 203(3.75,16.825) 204(3.25,16.825) 205(2.75,16.825) 206(2.25,16.825) 207(1.75,16.825) 208(1.25,16.825) 209(0.75,16.825) 210(0.25,16.825) 211(-0.25,16.825) 212(-0.75,16.825) 213(-1.25,16.825) 214(-1.75,16.825) 215(-2.25,16.825) 216(-2.75,16.825) 217(-3.25,16.825) 218(-3.75,16.825) 219(-4.25,16.825) 220(-4.75,16.825) 221(-5.25,16.825) 222(-5.75,16.825) 223(-6.25,16.825) 224(-6.75,16.825) 225(-7.25,16.825) 226(-7.75,16.825) 227(-8.25,16.825) 228(-8.75,16.825) 229(-9.25,16.825) 230(-9.75,16.825) 231(-10.25,16.825) 232(-10.75,16.825) 233(-11.25,16.825) 234(-11.75,16.825) 235(-12.25,16.825) 236(-12.75,16.825) 237(-13.25,16.825) 238(-13.75,16.825) 239(-14.25,16.825) 240(-14.75,16.825)
Top Overlay:
  circle w0.6: c-14.65,14.65 r0.3
  circle w0.25: c-16.825,15.425 r0.125
  lines w0.2: -15.65,-15.65 15.65,-15.65 15.65,15.65 -15.65,15.65 -15.65,-15.65
Mechanical 13:
  circle w0.1: c-15.1,15.1 r0.5
  lines w0.1: -16,-16 16,-16 16,16 -16,16 -16,-16
Mechanical 15:
  lines w0.1: -0.5,0 0.5,0 ; 0,-0.5 0,0.5 ; -17.7,-17.7 17.7,-17.7 17.7,17.7 -17.7,17.7 -17.7,-17.7
3D body: height 4.1, standoff 0, extent -16,-16 16,16

## HQG240_M [mm] "240-Pin Heat Sink Quad Flat Pack (HQG240) - Pb-Free, IPC Low Density"
height 4.1
pads (240):
  oval 2.1x0.3 smd: 1(-16.9,14.75) 2(-16.9,14.25) 3(-16.9,13.75) 4(-16.9,13.25) 5(-16.9,12.75) 6(-16.9,12.25) 7(-16.9,11.75) 8(-16.9,11.25) 9(-16.9,10.75) 10(-16.9,10.25) 11(-16.9,9.75) 12(-16.9,9.25) 13(-16.9,8.75) 14(-16.9,8.25) 15(-16.9,7.75) 16(-16.9,7.25) 17(-16.9,6.75) 18(-16.9,6.25) 19(-16.9,5.75) 20(-16.9,5.25) 21(-16.9,4.75) 22(-16.9,4.25) 23(-16.9,3.75) 24(-16.9,3.25) 25(-16.9,2.75) 26(-16.9,2.25) 27(-16.9,1.75) 28(-16.9,1.25) 29(-16.9,0.75) 30(-16.9,0.25) 31(-16.9,-0.25) 32(-16.9,-0.75) 33(-16.9,-1.25) 34(-16.9,-1.75) 35(-16.9,-2.25) 36(-16.9,-2.75) 37(-16.9,-3.25) 38(-16.9,-3.75) 39(-16.9,-4.25) 40(-16.9,-4.75) 41(-16.9,-5.25) 42(-16.9,-5.75) 43(-16.9,-6.25) 44(-16.9,-6.75) 45(-16.9,-7.25) 46(-16.9,-7.75) 47(-16.9,-8.25) 48(-16.9,-8.75) 49(-16.9,-9.25) 50(-16.9,-9.75) 51(-16.9,-10.25) 52(-16.9,-10.75) 53(-16.9,-11.25) 54(-16.9,-11.75) 55(-16.9,-12.25) 56(-16.9,-12.75) 57(-16.9,-13.25) 58(-16.9,-13.75) 59(-16.9,-14.25) 60(-16.9,-14.75) 121(16.9,-14.75) 122(16.9,-14.25) 123(16.9,-13.75) 124(16.9,-13.25) 125(16.9,-12.75) 126(16.9,-12.25) 127(16.9,-11.75) 128(16.9,-11.25) 129(16.9,-10.75) 130(16.9,-10.25) 131(16.9,-9.75) 132(16.9,-9.25) 133(16.9,-8.75) 134(16.9,-8.25) 135(16.9,-7.75) 136(16.9,-7.25) 137(16.9,-6.75) 138(16.9,-6.25) 139(16.9,-5.75) 140(16.9,-5.25) 141(16.9,-4.75) 142(16.9,-4.25) 143(16.9,-3.75) 144(16.9,-3.25) 145(16.9,-2.75) 146(16.9,-2.25) 147(16.9,-1.75) 148(16.9,-1.25) 149(16.9,-0.75) 150(16.9,-0.25) 151(16.9,0.25) 152(16.9,0.75) 153(16.9,1.25) 154(16.9,1.75) 155(16.9,2.25) 156(16.9,2.75) 157(16.9,3.25) 158(16.9,3.75) 159(16.9,4.25) 160(16.9,4.75) 161(16.9,5.25) 162(16.9,5.75) 163(16.9,6.25) 164(16.9,6.75) 165(16.9,7.25) 166(16.9,7.75) 167(16.9,8.25) 168(16.9,8.75) 169(16.9,9.25) 170(16.9,9.75) 171(16.9,10.25) 172(16.9,10.75) 173(16.9,11.25) 174(16.9,11.75) 175(16.9,12.25) 176(16.9,12.75) 177(16.9,13.25) 178(16.9,13.75) 179(16.9,14.25) 180(16.9,14.75)
  oval 0.3x2.1 smd: 61(-14.75,-16.9) 62(-14.25,-16.9) 63(-13.75,-16.9) 64(-13.25,-16.9) 65(-12.75,-16.9) 66(-12.25,-16.9) 67(-11.75,-16.9) 68(-11.25,-16.9) 69(-10.75,-16.9) 70(-10.25,-16.9) 71(-9.75,-16.9) 72(-9.25,-16.9) 73(-8.75,-16.9) 74(-8.25,-16.9) 75(-7.75,-16.9) 76(-7.25,-16.9) 77(-6.75,-16.9) 78(-6.25,-16.9) 79(-5.75,-16.9) 80(-5.25,-16.9) 81(-4.75,-16.9) 82(-4.25,-16.9) 83(-3.75,-16.9) 84(-3.25,-16.9) 85(-2.75,-16.9) 86(-2.25,-16.9) 87(-1.75,-16.9) 88(-1.25,-16.9) 89(-0.75,-16.9) 90(-0.25,-16.9) 91(0.25,-16.9) 92(0.75,-16.9) 93(1.25,-16.9) 94(1.75,-16.9) 95(2.25,-16.9) 96(2.75,-16.9) 97(3.25,-16.9) 98(3.75,-16.9) 99(4.25,-16.9) 100(4.75,-16.9) 101(5.25,-16.9) 102(5.75,-16.9) 103(6.25,-16.9) 104(6.75,-16.9) 105(7.25,-16.9) 106(7.75,-16.9) 107(8.25,-16.9) 108(8.75,-16.9) 109(9.25,-16.9) 110(9.75,-16.9) 111(10.25,-16.9) 112(10.75,-16.9) 113(11.25,-16.9) 114(11.75,-16.9) 115(12.25,-16.9) 116(12.75,-16.9) 117(13.25,-16.9) 118(13.75,-16.9) 119(14.25,-16.9) 120(14.75,-16.9) 181(14.75,16.9) 182(14.25,16.9) 183(13.75,16.9) 184(13.25,16.9) 185(12.75,16.9) 186(12.25,16.9) 187(11.75,16.9) 188(11.25,16.9) 189(10.75,16.9) 190(10.25,16.9) 191(9.75,16.9) 192(9.25,16.9) 193(8.75,16.9) 194(8.25,16.9) 195(7.75,16.9) 196(7.25,16.9) 197(6.75,16.9) 198(6.25,16.9) 199(5.75,16.9) 200(5.25,16.9) 201(4.75,16.9) 202(4.25,16.9) 203(3.75,16.9) 204(3.25,16.9) 205(2.75,16.9) 206(2.25,16.9) 207(1.75,16.9) 208(1.25,16.9) 209(0.75,16.9) 210(0.25,16.9) 211(-0.25,16.9) 212(-0.75,16.9) 213(-1.25,16.9) 214(-1.75,16.9) 215(-2.25,16.9) 216(-2.75,16.9) 217(-3.25,16.9) 218(-3.75,16.9) 219(-4.25,16.9) 220(-4.75,16.9) 221(-5.25,16.9) 222(-5.75,16.9) 223(-6.25,16.9) 224(-6.75,16.9) 225(-7.25,16.9) 226(-7.75,16.9) 227(-8.25,16.9) 228(-8.75,16.9) 229(-9.25,16.9) 230(-9.75,16.9) 231(-10.25,16.9) 232(-10.75,16.9) 233(-11.25,16.9) 234(-11.75,16.9) 235(-12.25,16.9) 236(-12.75,16.9) 237(-13.25,16.9) 238(-13.75,16.9) 239(-14.25,16.9) 240(-14.75,16.9)
Top Overlay:
  circle w0.6: c-14.45,14.45 r0.3
  circle w0.25: c-16.9,15.45 r0.125
  lines w0.2: -15.45,-15.45 15.45,-15.45 15.45,15.45 -15.45,15.45 -15.45,-15.45
Mechanical 13:
  circle w0.1: c-15.1,15.1 r0.5
  lines w0.1: -16,-16 16,-16 16,16 -16,16 -16,-16
Mechanical 15:
  lines w0.1: -0.5,0 0.5,0 ; 0,-0.5 0,0.5 ; -18.45,-18.45 18.45,-18.45 18.45,18.45 -18.45,18.45 -18.45,-18.45
3D body: height 4.1, standoff 0, extent -16,-16 16,16

## HQG240_N [mm] "240-Pin Heat Sink Quad Flat Pack (HQG240) - Pb-Free, IPC Medium Density"
height 4.1
pads (240):
  oval 1.8x0.3 smd: 1(-16.85,14.75) 2(-16.85,14.25) 3(-16.85,13.75) 4(-16.85,13.25) 5(-16.85,12.75) 6(-16.85,12.25) 7(-16.85,11.75) 8(-16.85,11.25) 9(-16.85,10.75) 10(-16.85,10.25) 11(-16.85,9.75) 12(-16.85,9.25) 13(-16.85,8.75) 14(-16.85,8.25) 15(-16.85,7.75) 16(-16.85,7.25) 17(-16.85,6.75) 18(-16.85,6.25) 19(-16.85,5.75) 20(-16.85,5.25) 21(-16.85,4.75) 22(-16.85,4.25) 23(-16.85,3.75) 24(-16.85,3.25) 25(-16.85,2.75) 26(-16.85,2.25) 27(-16.85,1.75) 28(-16.85,1.25) 29(-16.85,0.75) 30(-16.85,0.25) 31(-16.85,-0.25) 32(-16.85,-0.75) 33(-16.85,-1.25) 34(-16.85,-1.75) 35(-16.85,-2.25) 36(-16.85,-2.75) 37(-16.85,-3.25) 38(-16.85,-3.75) 39(-16.85,-4.25) 40(-16.85,-4.75) 41(-16.85,-5.25) 42(-16.85,-5.75) 43(-16.85,-6.25) 44(-16.85,-6.75) 45(-16.85,-7.25) 46(-16.85,-7.75) 47(-16.85,-8.25) 48(-16.85,-8.75) 49(-16.85,-9.25) 50(-16.85,-9.75) 51(-16.85,-10.25) 52(-16.85,-10.75) 53(-16.85,-11.25) 54(-16.85,-11.75) 55(-16.85,-12.25) 56(-16.85,-12.75) 57(-16.85,-13.25) 58(-16.85,-13.75) 59(-16.85,-14.25) 60(-16.85,-14.75) 121(16.85,-14.75) 122(16.85,-14.25) 123(16.85,-13.75) 124(16.85,-13.25) 125(16.85,-12.75) 126(16.85,-12.25) 127(16.85,-11.75) 128(16.85,-11.25) 129(16.85,-10.75) 130(16.85,-10.25) 131(16.85,-9.75) 132(16.85,-9.25) 133(16.85,-8.75) 134(16.85,-8.25) 135(16.85,-7.75) 136(16.85,-7.25) 137(16.85,-6.75) 138(16.85,-6.25) 139(16.85,-5.75) 140(16.85,-5.25) 141(16.85,-4.75) 142(16.85,-4.25) 143(16.85,-3.75) 144(16.85,-3.25) 145(16.85,-2.75) 146(16.85,-2.25) 147(16.85,-1.75) 148(16.85,-1.25) 149(16.85,-0.75) 150(16.85,-0.25) 151(16.85,0.25) 152(16.85,0.75) 153(16.85,1.25) 154(16.85,1.75) 155(16.85,2.25) 156(16.85,2.75) 157(16.85,3.25) 158(16.85,3.75) 159(16.85,4.25) 160(16.85,4.75) 161(16.85,5.25) 162(16.85,5.75) 163(16.85,6.25) 164(16.85,6.75) 165(16.85,7.25) 166(16.85,7.75) 167(16.85,8.25) 168(16.85,8.75) 169(16.85,9.25) 170(16.85,9.75) 171(16.85,10.25) 172(16.85,10.75) 173(16.85,11.25) 174(16.85,11.75) 175(16.85,12.25) 176(16.85,12.75) 177(16.85,13.25) 178(16.85,13.75) 179(16.85,14.25) 180(16.85,14.75)
  oval 0.3x1.8 smd: 61(-14.75,-16.85) 62(-14.25,-16.85) 63(-13.75,-16.85) 64(-13.25,-16.85) 65(-12.75,-16.85) 66(-12.25,-16.85) 67(-11.75,-16.85) 68(-11.25,-16.85) 69(-10.75,-16.85) 70(-10.25,-16.85) 71(-9.75,-16.85) 72(-9.25,-16.85) 73(-8.75,-16.85) 74(-8.25,-16.85) 75(-7.75,-16.85) 76(-7.25,-16.85) 77(-6.75,-16.85) 78(-6.25,-16.85) 79(-5.75,-16.85) 80(-5.25,-16.85) 81(-4.75,-16.85) 82(-4.25,-16.85) 83(-3.75,-16.85) 84(-3.25,-16.85) 85(-2.75,-16.85) 86(-2.25,-16.85) 87(-1.75,-16.85) 88(-1.25,-16.85) 89(-0.75,-16.85) 90(-0.25,-16.85) 91(0.25,-16.85) 92(0.75,-16.85) 93(1.25,-16.85) 94(1.75,-16.85) 95(2.25,-16.85) 96(2.75,-16.85) 97(3.25,-16.85) 98(3.75,-16.85) 99(4.25,-16.85) 100(4.75,-16.85) 101(5.25,-16.85) 102(5.75,-16.85) 103(6.25,-16.85) 104(6.75,-16.85) 105(7.25,-16.85) 106(7.75,-16.85) 107(8.25,-16.85) 108(8.75,-16.85) 109(9.25,-16.85) 110(9.75,-16.85) 111(10.25,-16.85) 112(10.75,-16.85) 113(11.25,-16.85) 114(11.75,-16.85) 115(12.25,-16.85) 116(12.75,-16.85) 117(13.25,-16.85) 118(13.75,-16.85) 119(14.25,-16.85) 120(14.75,-16.85) 181(14.75,16.85) 182(14.25,16.85) 183(13.75,16.85) 184(13.25,16.85) 185(12.75,16.85) 186(12.25,16.85) 187(11.75,16.85) 188(11.25,16.85) 189(10.75,16.85) 190(10.25,16.85) 191(9.75,16.85) 192(9.25,16.85) 193(8.75,16.85) 194(8.25,16.85) 195(7.75,16.85) 196(7.25,16.85) 197(6.75,16.85) 198(6.25,16.85) 199(5.75,16.85) 200(5.25,16.85) 201(4.75,16.85) 202(4.25,16.85) 203(3.75,16.85) 204(3.25,16.85) 205(2.75,16.85) 206(2.25,16.85) 207(1.75,16.85) 208(1.25,16.85) 209(0.75,16.85) 210(0.25,16.85) 211(-0.25,16.85) 212(-0.75,16.85) 213(-1.25,16.85) 214(-1.75,16.85) 215(-2.25,16.85) 216(-2.75,16.85) 217(-3.25,16.85) 218(-3.75,16.85) 219(-4.25,16.85) 220(-4.75,16.85) 221(-5.25,16.85) 222(-5.75,16.85) 223(-6.25,16.85) 224(-6.75,16.85) 225(-7.25,16.85) 226(-7.75,16.85) 227(-8.25,16.85) 228(-8.75,16.85) 229(-9.25,16.85) 230(-9.75,16.85) 231(-10.25,16.85) 232(-10.75,16.85) 233(-11.25,16.85) 234(-11.75,16.85) 235(-12.25,16.85) 236(-12.75,16.85) 237(-13.25,16.85) 238(-13.75,16.85) 239(-14.25,16.85) 240(-14.75,16.85)
Top Overlay:
  circle w0.6: c-14.55,14.55 r0.3
  circle w0.25: c-16.85,15.45 r0.125
  lines w0.2: -15.55,-15.55 15.55,-15.55 15.55,15.55 -15.55,15.55 -15.55,-15.55
Mechanical 13:
  circle w0.1: c-15.1,15.1 r0.5
  lines w0.1: -16,-16 16,-16 16,16 -16,16 -16,-16
Mechanical 15:
  lines w0.1: -0.5,0 0.5,0 ; 0,-0.5 0,0.5 ; -18,-18 18,-18 18,18 -18,18 -18,-18
3D body: height 4.1, standoff 0, extent -16,-16 16,16

## HT100_L [mm] "100-Pin Heat Sink Thin Quad Flat Pack (HT100), IPC High Density"
height 1.6
pads (100):
  oval 1.55x0.25 smd: 1(-7.525,6) 2(-7.525,5.5) 3(-7.525,5) 4(-7.525,4.5) 5(-7.525,4) 6(-7.525,3.5) 7(-7.525,3) 8(-7.525,2.5) 9(-7.525,2) 10(-7.525,1.5) 11(-7.525,1) 12(-7.525,0.5) 13(-7.525,0) 14(-7.525,-0.5) 15(-7.525,-1) 16(-7.525,-1.5) 17(-7.525,-2) 18(-7.525,-2.5) 19(-7.525,-3) 20(-7.525,-3.5) 21(-7.525,-4) 22(-7.525,-4.5) 23(-7.525,-5) 24(-7.525,-5.5) 25(-7.525,-6) 51(7.525,-6) 52(7.525,-5.5) 53(7.525,-5) 54(7.525,-4.5) 55(7.525,-4) 56(7.525,-3.5) 57(7.525,-3) 58(7.525,-2.5) 59(7.525,-2) 60(7.525,-1.5) 61(7.525,-1) 62(7.525,-0.5) 63(7.525,0) 64(7.525,0.5) 65(7.525,1) 66(7.525,1.5) 67(7.525,2) 68(7.525,2.5) 69(7.525,3) 70(7.525,3.5) 71(7.525,4) 72(7.525,4.5) 73(7.525,5) 74(7.525,5.5) 75(7.525,6)
  oval 0.25x1.55 smd: 26(-6,-7.525) 27(-5.5,-7.525) 28(-5,-7.525) 29(-4.5,-7.525) 30(-4,-7.525) 31(-3.5,-7.525) 32(-3,-7.525) 33(-2.5,-7.525) 34(-2,-7.525) 35(-1.5,-7.525) 36(-1,-7.525) 37(-0.5,-7.525) 38(0,-7.525) 39(0.5,-7.525) 40(1,-7.525) 41(1.5,-7.525) 42(2,-7.525) 43(2.5,-7.525) 44(3,-7.525) 45(3.5,-7.525) 46(4,-7.525) 47(4.5,-7.525) 48(5,-7.525) 49(5.5,-7.525) 50(6,-7.525) 76(6,7.525) 77(5.5,7.525) 78(5,7.525) 79(4.5,7.525) 80(4,7.525) 81(3.5,7.525) 82(3,7.525) 83(2.5,7.525) 84(2,7.525) 85(1.5,7.525) 86(1,7.525) 87(0.5,7.525) 88(0,7.525) 89(-0.5,7.525) 90(-1,7.525) 91(-1.5,7.525) 92(-2,7.525) 93(-2.5,7.525) 94(-3,7.525) 95(-3.5,7.525) 96(-4,7.525) 97(-4.5,7.525) 98(-5,7.525) 99(-5.5,7.525) 100(-6,7.525)
Top Overlay:
  circle w0.6: c-5.35,5.35 r0.3
  circle w0.25: c-7.525,6.675 r0.125
  lines w0.2: -6.35,-6.35 6.35,-6.35 6.35,6.35 -6.35,6.35 -6.35,-6.35
Mechanical 13:
  circle w0.1: c-6.1,6.1 r0.5
  lines w0.1: -7,-7 7,-7 7,7 -7,7 -7,-7
Mechanical 15:
  lines w0.1: -0.5,0 0.5,0 ; 0,-0.5 0,0.5 ; -8.4,-8.4 8.4,-8.4 8.4,8.4 -8.4,8.4 -8.4,-8.4
3D body: height 1.6, standoff 0, extent -7,-7 7,7

## HT100_M [mm] "100-Pin Heat Sink Thin Quad Flat Pack (HT100), IPC Low Density"
height 1.6
pads (100):
  oval 2.1x0.3 smd: 1(-7.6,6) 2(-7.6,5.5) 3(-7.6,5) 4(-7.6,4.5) 5(-7.6,4) 6(-7.6,3.5) 7(-7.6,3) 8(-7.6,2.5) 9(-7.6,2) 10(-7.6,1.5) 11(-7.6,1) 12(-7.6,0.5) 13(-7.6,0) 14(-7.6,-0.5) 15(-7.6,-1) 16(-7.6,-1.5) 17(-7.6,-2) 18(-7.6,-2.5) 19(-7.6,-3) 20(-7.6,-3.5) 21(-7.6,-4) 22(-7.6,-4.5) 23(-7.6,-5) 24(-7.6,-5.5) 25(-7.6,-6) 51(7.6,-6) 52(7.6,-5.5) 53(7.6,-5) 54(7.6,-4.5) 55(7.6,-4) 56(7.6,-3.5) 57(7.6,-3) 58(7.6,-2.5) 59(7.6,-2) 60(7.6,-1.5) 61(7.6,-1) 62(7.6,-0.5) 63(7.6,0) 64(7.6,0.5) 65(7.6,1) 66(7.6,1.5) 67(7.6,2) 68(7.6,2.5) 69(7.6,3) 70(7.6,3.5) 71(7.6,4) 72(7.6,4.5) 73(7.6,5) 74(7.6,5.5) 75(7.6,6)
  oval 0.3x2.1 smd: 26(-6,-7.6) 27(-5.5,-7.6) 28(-5,-7.6) 29(-4.5,-7.6) 30(-4,-7.6) 31(-3.5,-7.6) 32(-3,-7.6) 33(-2.5,-7.6) 34(-2,-7.6) 35(-1.5,-7.6) 36(-1,-7.6) 37(-0.5,-7.6) 38(0,-7.6) 39(0.5,-7.6) 40(1,-7.6) 41(1.5,-7.6) 42(2,-7.6) 43(2.5,-7.6) 44(3,-7.6) 45(3.5,-7.6) 46(4,-7.6) 47(4.5,-7.6) 48(5,-7.6) 49(5.5,-7.6) 50(6,-7.6) 76(6,7.6) 77(5.5,7.6) 78(5,7.6) 79(4.5,7.6) 80(4,7.6) 81(3.5,7.6) 82(3,7.6) 83(2.5,7.6) 84(2,7.6) 85(1.5,7.6) 86(1,7.6) 87(0.5,7.6) 88(0,7.6) 89(-0.5,7.6) 90(-1,7.6) 91(-1.5,7.6) 92(-2,7.6) 93(-2.5,7.6) 94(-3,7.6) 95(-3.5,7.6) 96(-4,7.6) 97(-4.5,7.6) 98(-5,7.6) 99(-5.5,7.6) 100(-6,7.6)
Top Overlay:
  circle w0.6: c-5.15,5.15 r0.3
  circle w0.25: c-7.6,6.7 r0.125
  lines w0.2: -6.15,-6.15 6.15,-6.15 6.15,6.15 -6.15,6.15 -6.15,-6.15
Mechanical 13:
  circle w0.1: c-6.1,6.1 r0.5
  lines w0.1: -7,-7 7,-7 7,7 -7,7 -7,-7
Mechanical 15:
  lines w0.1: -0.5,0 0.5,0 ; 0,-0.5 0,0.5 ; -9.15,-9.15 9.15,-9.15 9.15,9.15 -9.15,9.15 -9.15,-9.15
3D body: height 1.6, standoff 0, extent -7,-7 7,7

## HT100_N [mm] "100-Pin Heat Sink Thin Quad Flat Pack (HT100), IPC Medium Density"
height 1.6
pads (100):
  oval 1.8x0.3 smd: 1(-7.55,6) 2(-7.55,5.5) 3(-7.55,5) 4(-7.55,4.5) 5(-7.55,4) 6(-7.55,3.5) 7(-7.55,3) 8(-7.55,2.5) 9(-7.55,2) 10(-7.55,1.5) 11(-7.55,1) 12(-7.55,0.5) 13(-7.55,0) 14(-7.55,-0.5) 15(-7.55,-1) 16(-7.55,-1.5) 17(-7.55,-2) 18(-7.55,-2.5) 19(-7.55,-3) 20(-7.55,-3.5) 21(-7.55,-4) 22(-7.55,-4.5) 23(-7.55,-5) 24(-7.55,-5.5) 25(-7.55,-6) 51(7.55,-6) 52(7.55,-5.5) 53(7.55,-5) 54(7.55,-4.5) 55(7.55,-4) 56(7.55,-3.5) 57(7.55,-3) 58(7.55,-2.5) 59(7.55,-2) 60(7.55,-1.5) 61(7.55,-1) 62(7.55,-0.5) 63(7.55,0) 64(7.55,0.5) 65(7.55,1) 66(7.55,1.5) 67(7.55,2) 68(7.55,2.5) 69(7.55,3) 70(7.55,3.5) 71(7.55,4) 72(7.55,4.5) 73(7.55,5) 74(7.55,5.5) 75(7.55,6)
  oval 0.3x1.8 smd: 26(-6,-7.55) 27(-5.5,-7.55) 28(-5,-7.55) 29(-4.5,-7.55) 30(-4,-7.55) 31(-3.5,-7.55) 32(-3,-7.55) 33(-2.5,-7.55) 34(-2,-7.55) 35(-1.5,-7.55) 36(-1,-7.55) 37(-0.5,-7.55) 38(0,-7.55) 39(0.5,-7.55) 40(1,-7.55) 41(1.5,-7.55) 42(2,-7.55) 43(2.5,-7.55) 44(3,-7.55) 45(3.5,-7.55) 46(4,-7.55) 47(4.5,-7.55) 48(5,-7.55) 49(5.5,-7.55) 50(6,-7.55) 76(6,7.55) 77(5.5,7.55) 78(5,7.55) 79(4.5,7.55) 80(4,7.55) 81(3.5,7.55) 82(3,7.55) 83(2.5,7.55) 84(2,7.55) 85(1.5,7.55) 86(1,7.55) 87(0.5,7.55) 88(0,7.55) 89(-0.5,7.55) 90(-1,7.55) 91(-1.5,7.55) 92(-2,7.55) 93(-2.5,7.55) 94(-3,7.55) 95(-3.5,7.55) 96(-4,7.55) 97(-4.5,7.55) 98(-5,7.55) 99(-5.5,7.55) 100(-6,7.55)
Top Overlay:
  circle w0.6: c-5.25,5.25 r0.3
  circle w0.25: c-7.55,6.7 r0.125
  lines w0.2: -6.25,-6.25 6.25,-6.25 6.25,6.25 -6.25,6.25 -6.25,-6.25
Mechanical 13:
  circle w0.1: c-6.1,6.1 r0.5
  lines w0.1: -7,-7 7,-7 7,7 -7,7 -7,-7
Mechanical 15:
  lines w0.1: -0.5,0 0.5,0 ; 0,-0.5 0,0.5 ; -8.7,-8.7 8.7,-8.7 8.7,8.7 -8.7,8.7 -8.7,-8.7
3D body: height 1.6, standoff 0, extent -7,-7 7,7

## HT144_L [mm] "144-Pin Heat Sink Thin Quad Flat Pack (HT144), IPC High Density"
height 1.6
pads (144):
  oval 1.55x0.25 smd: 1(-10.525,8.75) 2(-10.525,8.25) 3(-10.525,7.75) 4(-10.525,7.25) 5(-10.525,6.75) 6(-10.525,6.25) 7(-10.525,5.75) 8(-10.525,5.25) 9(-10.525,4.75) 10(-10.525,4.25) 11(-10.525,3.75) 12(-10.525,3.25) 13(-10.525,2.75) 14(-10.525,2.25) 15(-10.525,1.75) 16(-10.525,1.25) 17(-10.525,0.75) 18(-10.525,0.25) 19(-10.525,-0.25) 20(-10.525,-0.75) 21(-10.525,-1.25) 22(-10.525,-1.75) 23(-10.525,-2.25) 24(-10.525,-2.75) 25(-10.525,-3.25) 26(-10.525,-3.75) 27(-10.525,-4.25) 28(-10.525,-4.75) 29(-10.525,-5.25) 30(-10.525,-5.75) 31(-10.525,-6.25) 32(-10.525,-6.75) 33(-10.525,-7.25) 34(-10.525,-7.75) 35(-10.525,-8.25) 36(-10.525,-8.75) 73(10.525,-8.75) 74(10.525,-8.25) 75(10.525,-7.75) 76(10.525,-7.25) 77(10.525,-6.75) 78(10.525,-6.25) 79(10.525,-5.75) 80(10.525,-5.25) 81(10.525,-4.75) 82(10.525,-4.25) 83(10.525,-3.75) 84(10.525,-3.25) 85(10.525,-2.75) 86(10.525,-2.25) 87(10.525,-1.75) 88(10.525,-1.25) 89(10.525,-0.75) 90(10.525,-0.25) 91(10.525,0.25) 92(10.525,0.75) 93(10.525,1.25) 94(10.525,1.75) 95(10.525,2.25) 96(10.525,2.75) 97(10.525,3.25) 98(10.525,3.75) 99(10.525,4.25) 100(10.525,4.75) 101(10.525,5.25) 102(10.525,5.75) 103(10.525,6.25) 104(10.525,6.75) 105(10.525,7.25) 106(10.525,7.75) 107(10.525,8.25) 108(10.525,8.75)
  oval 0.25x1.55 smd: 37(-8.75,-10.525) 38(-8.25,-10.525) 39(-7.75,-10.525) 40(-7.25,-10.525) 41(-6.75,-10.525) 42(-6.25,-10.525) 43(-5.75,-10.525) 44(-5.25,-10.525) 45(-4.75,-10.525) 46(-4.25,-10.525) 47(-3.75,-10.525) 48(-3.25,-10.525) 49(-2.75,-10.525) 50(-2.25,-10.525) 51(-1.75,-10.525) 52(-1.25,-10.525) 53(-0.75,-10.525) 54(-0.25,-10.525) 55(0.25,-10.525) 56(0.75,-10.525) 57(1.25,-10.525) 58(1.75,-10.525) 59(2.25,-10.525) 60(2.75,-10.525) 61(3.25,-10.525) 62(3.75,-10.525) 63(4.25,-10.525) 64(4.75,-10.525) 65(5.25,-10.525) 66(5.75,-10.525) 67(6.25,-10.525) 68(6.75,-10.525) 69(7.25,-10.525) 70(7.75,-10.525) 71(8.25,-10.525) 72(8.75,-10.525) 109(8.75,10.525) 110(8.25,10.525) 111(7.75,10.525) 112(7.25,10.525) 113(6.75,10.525) 114(6.25,10.525) 115(5.75,10.525) 116(5.25,10.525) 117(4.75,10.525) 118(4.25,10.525) 119(3.75,10.525) 120(3.25,10.525) 121(2.75,10.525) 122(2.25,10.525) 123(1.75,10.525) 124(1.25,10.525) 125(0.75,10.525) 126(0.25,10.525) 127(-0.25,10.525) 128(-0.75,10.525) 129(-1.25,10.525) 130(-1.75,10.525) 131(-2.25,10.525) 132(-2.75,10.525) 133(-3.25,10.525) 134(-3.75,10.525) 135(-4.25,10.525) 136(-4.75,10.525) 137(-5.25,10.525) 138(-5.75,10.525) 139(-6.25,10.525) 140(-6.75,10.525) 141(-7.25,10.525) 142(-7.75,10.525) 143(-8.25,10.525) 144(-8.75,10.525)
Top Overlay:
  circle w0.25: c-10.525,9.425 r0.125
  circle w0.6: c-8.35,8.35 r0.3
  lines w0.2: -9.35,-9.35 -9.35,9.35 9.35,9.35 9.35,-9.35 -9.35,-9.35
Mechanical 13:
  circle w0.1: c-9.1,9.1 r0.5
  lines w0.1: -10,-10 -10,10 10,10 10,-10 -10,-10
Mechanical 15:
  lines w0.1: -0.5,0 0.5,0 ; 0,-0.5 0,0.5 ; -11.4,-11.4 -11.4,11.4 11.4,11.4 11.4,-11.4 -11.4,-11.4
3D body: height 1.6, standoff 0, extent -10,-10 10,10

## HT144_M [mm] "144-Pin Heat Sink Thin Quad Flat Pack (HT144), IPC Low Density"
height 1.6
pads (144):
  oval 2.1x0.3 smd: 1(-10.6,8.75) 2(-10.6,8.25) 3(-10.6,7.75) 4(-10.6,7.25) 5(-10.6,6.75) 6(-10.6,6.25) 7(-10.6,5.75) 8(-10.6,5.25) 9(-10.6,4.75) 10(-10.6,4.25) 11(-10.6,3.75) 12(-10.6,3.25) 13(-10.6,2.75) 14(-10.6,2.25) 15(-10.6,1.75) 16(-10.6,1.25) 17(-10.6,0.75) 18(-10.6,0.25) 19(-10.6,-0.25) 20(-10.6,-0.75) 21(-10.6,-1.25) 22(-10.6,-1.75) 23(-10.6,-2.25) 24(-10.6,-2.75) 25(-10.6,-3.25) 26(-10.6,-3.75) 27(-10.6,-4.25) 28(-10.6,-4.75) 29(-10.6,-5.25) 30(-10.6,-5.75) 31(-10.6,-6.25) 32(-10.6,-6.75) 33(-10.6,-7.25) 34(-10.6,-7.75) 35(-10.6,-8.25) 36(-10.6,-8.75) 73(10.6,-8.75) 74(10.6,-8.25) 75(10.6,-7.75) 76(10.6,-7.25) 77(10.6,-6.75) 78(10.6,-6.25) 79(10.6,-5.75) 80(10.6,-5.25) 81(10.6,-4.75) 82(10.6,-4.25) 83(10.6,-3.75) 84(10.6,-3.25) 85(10.6,-2.75) 86(10.6,-2.25) 87(10.6,-1.75) 88(10.6,-1.25) 89(10.6,-0.75) 90(10.6,-0.25) 91(10.6,0.25) 92(10.6,0.75) 93(10.6,1.25) 94(10.6,1.75) 95(10.6,2.25) 96(10.6,2.75) 97(10.6,3.25) 98(10.6,3.75) 99(10.6,4.25) 100(10.6,4.75) 101(10.6,5.25) 102(10.6,5.75) 103(10.6,6.25) 104(10.6,6.75) 105(10.6,7.25) 106(10.6,7.75) 107(10.6,8.25) 108(10.6,8.75)
  oval 0.3x2.1 smd: 37(-8.75,-10.6) 38(-8.25,-10.6) 39(-7.75,-10.6) 40(-7.25,-10.6) 41(-6.75,-10.6) 42(-6.25,-10.6) 43(-5.75,-10.6) 44(-5.25,-10.6) 45(-4.75,-10.6) 46(-4.25,-10.6) 47(-3.75,-10.6) 48(-3.25,-10.6) 49(-2.75,-10.6) 50(-2.25,-10.6) 51(-1.75,-10.6) 52(-1.25,-10.6) 53(-0.75,-10.6) 54(-0.25,-10.6) 55(0.25,-10.6) 56(0.75,-10.6) 57(1.25,-10.6) 58(1.75,-10.6) 59(2.25,-10.6) 60(2.75,-10.6) 61(3.25,-10.6) 62(3.75,-10.6) 63(4.25,-10.6) 64(4.75,-10.6) 65(5.25,-10.6) 66(5.75,-10.6) 67(6.25,-10.6) 68(6.75,-10.6) 69(7.25,-10.6) 70(7.75,-10.6) 71(8.25,-10.6) 72(8.75,-10.6) 109(8.75,10.6) 110(8.25,10.6) 111(7.75,10.6) 112(7.25,10.6) 113(6.75,10.6) 114(6.25,10.6) 115(5.75,10.6) 116(5.25,10.6) 117(4.75,10.6) 118(4.25,10.6) 119(3.75,10.6) 120(3.25,10.6) 121(2.75,10.6) 122(2.25,10.6) 123(1.75,10.6) 124(1.25,10.6) 125(0.75,10.6) 126(0.25,10.6) 127(-0.25,10.6) 128(-0.75,10.6) 129(-1.25,10.6) 130(-1.75,10.6) 131(-2.25,10.6) 132(-2.75,10.6) 133(-3.25,10.6) 134(-3.75,10.6) 135(-4.25,10.6) 136(-4.75,10.6) 137(-5.25,10.6) 138(-5.75,10.6) 139(-6.25,10.6) 140(-6.75,10.6) 141(-7.25,10.6) 142(-7.75,10.6) 143(-8.25,10.6) 144(-8.75,10.6)
Top Overlay:
  circle w0.6: c-8.15,8.15 r0.3
  circle w0.25: c-10.6,9.45 r0.125
  lines w0.2: -9.15,-9.15 9.15,-9.15 9.15,9.15 -9.15,9.15 -9.15,-9.15
Mechanical 13:
  circle w0.1: c-9.1,9.1 r0.5
  lines w0.1: -10,-10 10,-10 10,10 -10,10 -10,-10
Mechanical 15:
  lines w0.1: -0.5,0 0.5,0 ; 0,-0.5 0,0.5 ; -12.15,-12.15 12.15,-12.15 12.15,12.15 -12.15,12.15 -12.15,-12.15
3D body: height 1.6, standoff 0, extent -10,-10 10,10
